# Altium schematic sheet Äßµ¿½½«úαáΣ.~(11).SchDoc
size A4
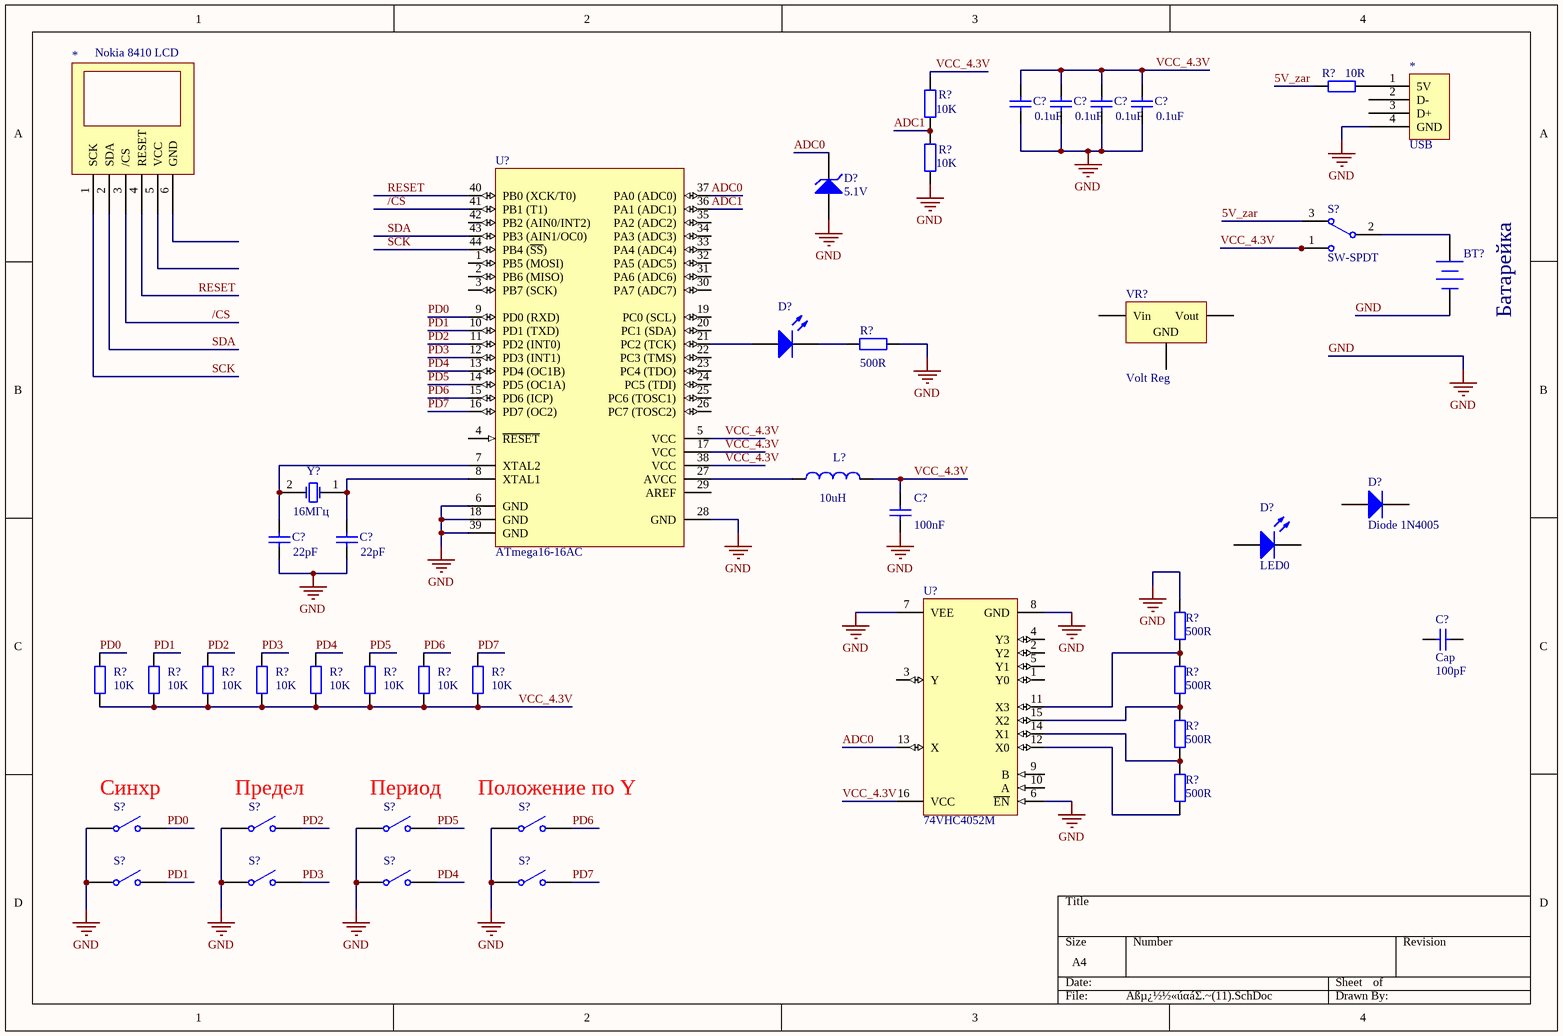
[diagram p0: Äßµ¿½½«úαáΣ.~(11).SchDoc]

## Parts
(Parts that share a designator on the sheet are numbered #1, #2 ... from top to bottom, then left to right.)
*#1  USB
*#2  Nokia 8410 LCD
BT?  Батарейка  [BAT-2]
C?#1  value 0.1uF  [RAD-0.3]  (hidden comment: Cap)
C?#2  value 0.1uF  [RAD-0.3]  (hidden comment: Cap)
C?#3  value 0.1uF  [RAD-0.3]  (hidden comment: Cap)
C?#4  value 0.1uF  [RAD-0.3]  (hidden comment: Cap)
C?#5  value 100nF  [RAD-0.3]  (hidden comment: Cap)
C?#6  value 22pF  [RAD-0.3]  (hidden comment: Cap)
C?#7  value 22pF  [RAD-0.3]  (hidden comment: Cap)
C?#8  Cap  value 100pF  [RAD-0.3]
D?#1  5.1V  [DIODE-0.7]
D?#2  LED0  [LED-0]  (value not drawn)
D?#3  Diode 1N4005  [DIO10.46-5.3x2.8]
D?#4  LED0  [LED-0]
L?  value 10uH  [INDC1005AL]  (hidden comment: Inductor)
R?#1  value 10R  [AXIAL-0.4]  (hidden comment: Res2)
R?#2  value 10K  [AXIAL-0.4]  (hidden comment: Res2)
R?#3  value 10K  [AXIAL-0.4]  (hidden comment: Res2)
R?#4  value 500R  [AXIAL-0.4]  (hidden comment: Res2)
R?#5  value 500R  [AXIAL-0.4]  (hidden comment: Res2)
R?#6  value 10K  [AXIAL-0.4]  (hidden comment: Res2)
R?#7  value 10K  [AXIAL-0.4]  (hidden comment: Res2)
R?#8  value 10K  [AXIAL-0.4]  (hidden comment: Res2)
R?#9  value 10K  [AXIAL-0.4]  (hidden comment: Res2)
R?#10  value 10K  [AXIAL-0.4]  (hidden comment: Res2)
R?#11  value 10K  [AXIAL-0.4]  (hidden comment: Res2)
R?#12  value 10K  [AXIAL-0.4]  (hidden comment: Res2)
R?#13  value 10K  [AXIAL-0.4]  (hidden comment: Res2)
R?#14  value 500R  [AXIAL-0.4]  (hidden comment: Res2)
R?#15  value 500R  [AXIAL-0.4]  (hidden comment: Res2)
R?#16  value 500R  [AXIAL-0.4]  (hidden comment: Res2)
S?#1  SW-SPDT  [TL36WW15050]
S?#2  SW-SPST  [SPST-2]  (value not drawn)
S?#3  SW-SPST  [SPST-2]  (value not drawn)
S?#4  SW-SPST  [SPST-2]  (value not drawn)
S?#5  SW-SPST  [SPST-2]  (value not drawn)
S?#6  SW-SPST  [SPST-2]  (value not drawn)
S?#7  SW-SPST  [SPST-2]  (value not drawn)
S?#8  SW-SPST  [SPST-2]  (value not drawn)
S?#9  SW-SPST  [SPST-2]  (value not drawn)
U?#1  ATmega16-16AC  [44A_N]
U?#2  74VHC4052M  [M16A_N]
VR?  Volt Reg  [TO254P1510-3_4N]
Y?  16МГц  [BCY-W2/D3.1]

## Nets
GND: *#1.4(GND) BT?.2(-) C?#1.1 C?#2.1 C?#3.1 C?#4.1 C?#5.1 C?#6.1 C?#7.1 D?#1.1(A) R?#3.1 R?#4.2 R?#5.2 S?#2.1(COMMON) S?#3.1(COMMON) S?#4.1(COMMON) S?#5.1(COMMON) S?#6.1(COMMON) S?#7.1(COMMON) S?#8.1(COMMON) S?#9.1(COMMON) U?#1.6(GND) U?#1.18(GND) U?#1.28(GND) U?#1.39(GND) U?#2.6(~{EN}) U?#2.7(VEE) U?#2.8(GND)
5V_zar: R?#1.1 S?#1.3
/CS: *#2.3(/CS) U?#1.41(PB1_(T1))
ADC0: D?#1.2(K) U?#1.37(PA0_(ADC0)) U?#2.13(X)
ADC1: R?#2.1 R?#3.2 U?#1.36(PA1_(ADC1))
PD0: R?#6.2 S?#2.2(NO) U?#1.9(PD0_(RXD))
PD1: R?#7.2 S?#6.2(NO) U?#1.10(PD1_(TXD))
PD2: R?#8.2 S?#3.2(NO) U?#1.11(PD2_(INT0))
PD3: R?#9.2 S?#7.2(NO) U?#1.12(PD3_(INT1))
PD4: R?#10.2 S?#8.2(NO) U?#1.13(PD4_(OC1B))
PD5: R?#11.2 S?#4.2(NO) U?#1.14(PD5_(OC1A))
PD6: R?#12.2 S?#5.2(NO) U?#1.15(PD6_(ICP))
PD7: R?#13.2 S?#9.2(NO) U?#1.16(PD7_(OC2))
RESET: *#2.4(RESET) U?#1.40(PB0_(XCK/T0))
SCK: *#2.1(SCK) U?#1.44(PB4_(~{SS}))
SDA: *#2.2(SDA) U?#1.43(PB3_(AIN1/OC0))
VCC_4.3V: C?#1.2 C?#2.2 C?#3.2 C?#4.2 C?#5.2 L?.2 R?#2.2 R?#6.1 R?#7.1 R?#8.1 R?#9.1 R?#10.1 R?#11.1 R?#12.1 R?#13.1 S?#1.1 U?#1.5(VCC) U?#1.17(VCC) U?#1.38(VCC) U?#2.16(VCC)
Net*#1_1: *#1.1(5V) R?#1.2
NetBT?_1: BT?.1(+) S?#1.2
NetC?#6_2: C?#6.2 U?#1.7(XTAL2) Y?.2(OSC2)
NetC?#7_2: C?#7.2 U?#1.8(XTAL1) Y?.1(OSC1)
NetD?#2_1: D?#2.1(A) U?#1.21(PC2_(TCK))
NetD?#2_2: D?#2.2(K) R?#4.1
NetL?_1: L?.1 U?#1.27(AVCC)
NetR?#5_1: R?#5.1 R?#14.2 U?#2.11(X3)
NetR?#14_1: R?#14.1 R?#15.2 U?#2.15(X2)
NetR?#15_1: R?#15.1 R?#16.2 U?#2.14(X1)
NetR?#16_1: R?#16.1 U?#2.12(X0)

Not connected (* = marked no-connect by the designer): *#1 2(D-) 3(D+); *#2 5(VCC) 6(GND); C?#8 1 2; D?#3 1(A) 2(K); D?#4 1(A) 2(K); U?#1 1(PB5_(MOSI)) 2(PB6_(MISO)) 3(PB7_(SCK)) 4(~{RESET}) 19(PC0_(SCL)) 20(PC1_(SDA)) 22(PC3_(TMS)) 23(PC4_(TDO)) 24(PC5_(TDI)) 25(PC6_(TOSC1)) 26(PC7_(TOSC2)) 29(AREF) 30(PA7_(ADC7)) 31(PA6_(ADC6)) 32(PA5_(ADC5)) 33(PA4_(ADC4)) 34(PA3_(ADC3)) 35(PA2_(ADC2)) 42(PB2_(AIN0/INT2)); U?#2 1(Y0) 2(Y2) 3(Y) 4(Y3) 5(Y1) 9(B) 10(A); VR? 1(Vin) 2(GND) 3(Vout)

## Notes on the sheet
- (near S?#2) Синхр
- (near S?#3) Предел
- (near S?#4) Период
- (near S?#5) Положение по Y

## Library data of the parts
*#2 = Component_1
BT? = Battery: Multicell Battery
C?#1-C?#8 = Cap: Capacitor
D?#1 = D Zener: Zener Diode
D?#2 D?#4 = LED0: Typical INFRARED GaAs LED
D?#3 = Diode 1N4005: 1 Amp General Purpose Rectifier
L? = Inductor: Code_IEC: 1005
R?#1-R?#16 = Res2: Resistor
S?#1 = SW-SPDT: SPDT Subminiature Toggle Switch, Right Angle Mounting, Vertical Actuation
S?#2-S?#9 = SW-SPST: Single-Pole, Single-Throw Switch
U?#1 = ATmega16-16AC: 8-Bit AVR Microcontroller with 16K Bytes of In-System Programmable Flash Memory
U?#2 = 74VHC4052M: Dual 4-Channel Analog Multiplexer
VR? = Volt Reg: Voltage Regulator
Y? = XTAL: Crystal Oscillator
